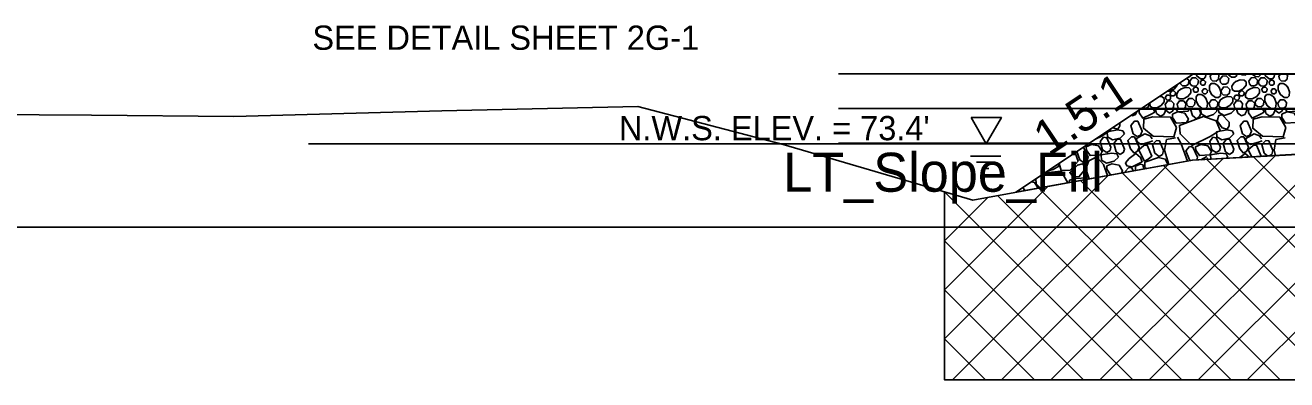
# Model space of a CAD drawing. Extents: x -14026 to 1303, y -10 to 9533.
# Drawn here: x 79.05 to 115.37, y 5995.6 to 6005.82 of the extents above; entities that cross this region are included whole.
import ezdxf

# ---------------------------------------------------------------- set-up
doc = ezdxf.new("R2010")
doc.units = 0
for name, color, linetype in [('Exist Cross Section Cell', 7, 'Continuous'), ('Exist XS Ground Line', 7, 'Continuous'), ('Old_Level_10', 7, 'Continuous'), ('Prop XS Side Slope Text', 7, 'Continuous'), ('Scratch_Level_0', 7, 'Continuous'), ('Scratch_Level_1', 7, 'Continuous'), ('Scratch_Level_3', 7, 'Continuous'), ('Scratch_Level_5', 7, 'Continuous')]:
    doc.layers.add(name, color=color, linetype=linetype)

msp = doc.modelspace()

# ---------------------------------------------------------------- linework, layer by layer
at = {"layer": 'Exist Cross Section Cell'}
msp.add_line((0, 6000), (150, 6000), dxfattribs=at)
at = {"layer": 'Exist XS Ground Line'}
msp.add_lwpolyline([(73.426, 6003.275), (80.955, 6003.228), (85.056, 6003.187), (91.045, 6003.354), (96.686, 6003.483), (100.866, 6002.389), (106.327, 6000.781), (112.649, 6001.933), (119.248, 6002.291)], dxfattribs=at)
at = {"layer": 'Old_Level_10'}
for p, q in [((107.565, 6001.007), (112.655, 6004.4)), ((113.16, 6004.354), (113.193, 6004.401)), ((115.139, 6004.354), (115.174, 6004.404)), ((111.155, 6003.4), (125.804, 6003.4)), ((111.531, 6003.4), (111.565, 6003.319)), ((113.345, 6003.4), (113.351, 6003.349)), ((113.858, 6003.4), (113.86, 6003.387)), ((114.678, 6003.4), (114.713, 6003.319)), ((110.921, 6003.207), (110.894, 6003.226)), ((110.286, 6002.821), (110.306, 6002.77)), ((112.889, 6001.946), (113.069, 6002.038)), ((113.07, 6002), (113.106, 6001.957)), ((113.668, 6002.021), (113.63, 6001.986)), ((108.784, 6001.82), (108.809, 6001.764)), ((109.106, 6001.287), (109.11, 6001.355)), ((107.828, 6001.055), (107.769, 6001.143))]:
    msp.add_line(p, q, dxfattribs=at)
msp.add_lwpolyline([(119.248, 6002.291), (117.01, 6002.178), (112.649, 6001.933), (107.565, 6001.007), (112.655, 6004.4), (127.732, 6004.426), (125.916, 6003.46), (123.411, 6002.115)], close=True, dxfattribs=at)
for points in [[(112.216, 6004.107), (112.215, 6004.097), (112.132, 6003.99), (112.003, 6003.926), (111.942, 6003.925)], [(112.492, 6004.291), (112.545, 6004.236), (112.534, 6004.128), (112.468, 6004.073), (112.362, 6004.08), (112.312, 6004.129), (112.305, 6004.167)], [(112.602, 6004.365), (112.577, 6004.339), (112.563, 6004.339)], [(112.572, 6004.208), (112.64, 6004.303), (112.747, 6004.309), (112.822, 6004.232), (112.811, 6004.124), (112.745, 6004.069), (112.639, 6004.076), (112.589, 6004.125), (112.573, 6004.208)], [(113.034, 6004.401), (113.028, 6004.333), (112.976, 6004.278), (112.882, 6004.28), (112.775, 6004.363), (112.757, 6004.4)], [(112.878, 6004.178), (112.919, 6004.236), (112.983, 6004.239), (113.028, 6004.193), (113.021, 6004.128), (112.982, 6004.095), (112.918, 6004.099), (112.888, 6004.128), (112.878, 6004.178)], [(113.417, 6004.033), (113.467, 6003.907), (113.457, 6003.792), (113.405, 6003.737), (113.311, 6003.739), (113.204, 6003.822), (113.14, 6003.951), (113.138, 6004.072), (113.187, 6004.14), (113.283, 6004.147), (113.37, 6004.091), (113.42, 6004.028)], [(113.387, 6004.401), (113.409, 6004.379), (113.399, 6004.27), (113.332, 6004.215), (113.226, 6004.223), (113.176, 6004.271), (113.16, 6004.354)], [(113.444, 6004.259), (113.512, 6004.355), (113.619, 6004.361), (113.694, 6004.284), (113.683, 6004.175), (113.616, 6004.12), (113.51, 6004.128), (113.461, 6004.176), (113.444, 6004.259)], [(113.927, 6004.402), (113.925, 6004.377), (113.872, 6004.322), (113.779, 6004.324), (113.679, 6004.402)], [(113.9, 6004.203), (114.025, 6004.253), (114.141, 6004.243), (114.196, 6004.191), (114.194, 6004.097), (114.111, 6003.99), (113.982, 6003.926), (113.861, 6003.924), (113.792, 6003.972), (113.786, 6004.069), (113.841, 6004.156), (113.905, 6004.206)], [(114.2, 6004.403), (114.178, 6004.384), (114.072, 6004.392), (114.061, 6004.403)], [(114.275, 6004.212), (114.342, 6004.307), (114.449, 6004.314), (114.524, 6004.236), (114.513, 6004.128), (114.447, 6004.073), (114.341, 6004.08), (114.291, 6004.129), (114.275, 6004.212)], [(114.609, 6004.403), (114.608, 6004.394), (114.556, 6004.339), (114.462, 6004.341), (114.382, 6004.403)], [(114.551, 6004.208), (114.618, 6004.303), (114.726, 6004.309), (114.8, 6004.232), (114.79, 6004.124), (114.723, 6004.069), (114.617, 6004.076), (114.567, 6004.125), (114.551, 6004.208)], [(115.013, 6004.404), (115.007, 6004.333), (114.954, 6004.278), (114.861, 6004.28), (114.754, 6004.363), (114.734, 6004.404)], [(114.857, 6004.178), (114.897, 6004.236), (114.962, 6004.239), (115.007, 6004.193), (115, 6004.128), (114.96, 6004.095), (114.897, 6004.099), (114.867, 6004.128), (114.857, 6004.178)], [(115.396, 6004.033), (115.446, 6003.907), (115.436, 6003.792), (115.384, 6003.737), (115.29, 6003.739), (115.183, 6003.822), (115.119, 6003.951), (115.117, 6004.072), (115.165, 6004.14), (115.262, 6004.147), (115.348, 6004.091), (115.399, 6004.028)], [(115.363, 6004.405), (115.388, 6004.379), (115.377, 6004.27), (115.311, 6004.215), (115.205, 6004.223), (115.155, 6004.271), (115.139, 6004.354)], [(111.708, 6003.769), (111.784, 6003.762), (111.839, 6003.71), (111.837, 6003.616), (111.754, 6003.51), (111.625, 6003.445), (111.503, 6003.443), (111.435, 6003.492), (111.429, 6003.583)], [(111.873, 6003.749), (111.913, 6003.807), (111.977, 6003.81), (112.022, 6003.764), (112.016, 6003.699), (111.976, 6003.666), (111.912, 6003.671), (111.882, 6003.7), (111.873, 6003.749)], [(112.011, 6003.866), (112.052, 6003.923), (112.116, 6003.927), (112.161, 6003.881), (112.154, 6003.816), (112.115, 6003.783), (112.051, 6003.787), (112.021, 6003.816), (112.011, 6003.866)], [(112.311, 6003.978), (112.437, 6004.028), (112.552, 6004.018), (112.607, 6003.966), (112.606, 6003.872), (112.522, 6003.766), (112.393, 6003.701), (112.272, 6003.699), (112.204, 6003.748), (112.197, 6003.844), (112.253, 6003.931), (112.316, 6003.982)], [(112.67, 6003.976), (112.711, 6004.034), (112.775, 6004.037), (112.82, 6003.991), (112.813, 6003.926), (112.774, 6003.893), (112.71, 6003.898), (112.68, 6003.927), (112.67, 6003.976)], [(113.037, 6003.716), (113.087, 6003.59), (113.077, 6003.475), (113.024, 6003.42), (112.931, 6003.421), (112.824, 6003.505), (112.76, 6003.633), (112.758, 6003.755), (112.806, 6003.823), (112.903, 6003.83), (112.989, 6003.774), (113.04, 6003.711)], [(112.935, 6003.929), (112.975, 6003.987), (113.04, 6003.99), (113.085, 6003.944), (113.078, 6003.879), (113.038, 6003.846), (112.975, 6003.85), (112.945, 6003.879), (112.935, 6003.929)], [(113.521, 6003.722), (113.647, 6003.772), (113.763, 6003.762), (113.817, 6003.71), (113.816, 6003.616), (113.732, 6003.51), (113.604, 6003.445), (113.482, 6003.443), (113.414, 6003.492), (113.407, 6003.588), (113.463, 6003.675), (113.526, 6003.725)], [(113.474, 6003.945), (113.541, 6004.04), (113.649, 6004.046), (113.723, 6003.969), (113.713, 6003.861), (113.646, 6003.805), (113.54, 6003.813), (113.49, 6003.861), (113.474, 6003.945)], [(113.851, 6003.749), (113.892, 6003.807), (113.956, 6003.81), (114.001, 6003.764), (113.994, 6003.699), (113.955, 6003.666), (113.891, 6003.671), (113.861, 6003.7), (113.851, 6003.749)], [(113.99, 6003.866), (114.03, 6003.923), (114.095, 6003.927), (114.14, 6003.881), (114.133, 6003.816), (114.093, 6003.783), (114.03, 6003.787), (114, 6003.816), (113.99, 6003.866)], [(114.29, 6003.978), (114.416, 6004.028), (114.531, 6004.018), (114.586, 6003.966), (114.584, 6003.872), (114.501, 6003.766), (114.372, 6003.701), (114.251, 6003.699), (114.182, 6003.748), (114.176, 6003.844), (114.231, 6003.931), (114.295, 6003.982)], [(114.649, 6003.976), (114.689, 6004.034), (114.754, 6004.037), (114.798, 6003.991), (114.792, 6003.926), (114.752, 6003.893), (114.689, 6003.898), (114.659, 6003.927), (114.649, 6003.976)], [(115.015, 6003.716), (115.065, 6003.59), (115.055, 6003.475), (115.003, 6003.42), (114.909, 6003.421), (114.803, 6003.505), (114.738, 6003.633), (114.736, 6003.755), (114.785, 6003.823), (114.882, 6003.83), (114.968, 6003.774), (115.019, 6003.711)], [(114.914, 6003.929), (114.954, 6003.987), (115.019, 6003.99), (115.063, 6003.944), (115.057, 6003.879), (115.017, 6003.846), (114.953, 6003.85), (114.924, 6003.879), (114.914, 6003.929)], [(111.401, 6003.564), (111.393, 6003.491), (111.327, 6003.436), (111.221, 6003.443), (111.22, 6003.444)], [(111.734, 6003.203), (111.618, 6003.28), (111.592, 6003.4)], [(111.861, 6003.4), (111.878, 6003.359), (111.826, 6003.245), (111.734, 6003.203)], [(111.868, 6003.539), (111.935, 6003.635), (112.043, 6003.641), (112.117, 6003.564), (112.107, 6003.455), (112.042, 6003.402)], [(112.019, 6003.402), (111.934, 6003.408), (111.884, 6003.456), (111.868, 6003.539)], [(111.986, 6003.285), (111.882, 6003.374), (111.877, 6003.4)], [(112.108, 6003.4), (112.077, 6003.345), (111.986, 6003.285)], [(112.555, 6003.4), (112.527, 6003.35), (112.228, 6003.331), (112.186, 6003.4)], [(112.215, 6003.543), (112.282, 6003.639), (112.39, 6003.645), (112.464, 6003.568), (112.453, 6003.459), (112.387, 6003.404), (112.281, 6003.412), (112.231, 6003.46), (112.215, 6003.543)], [(112.476, 6003.613), (112.543, 6003.709), (112.65, 6003.715), (112.725, 6003.638), (112.714, 6003.529), (112.648, 6003.474), (112.542, 6003.482), (112.492, 6003.53), (112.476, 6003.613)], [(112.765, 6003.128), (112.649, 6003.217), (112.599, 6003.4)], [(112.842, 6003.4), (112.89, 6003.289), (112.856, 6003.194), (112.765, 6003.128)], [(113.351, 6003.349), (113.261, 6003.251), (113.057, 6003.18), (112.904, 6003.268), (112.893, 6003.4)], [(113.134, 6003.575), (113.201, 6003.67), (113.308, 6003.677), (113.383, 6003.599), (113.372, 6003.491), (113.306, 6003.436), (113.2, 6003.443), (113.15, 6003.492), (113.134, 6003.575)], [(113.86, 6003.387), (113.77, 6003.289), (113.566, 6003.218), (113.413, 6003.306), (113.405, 6003.4)], [(113.847, 6003.539), (113.914, 6003.635), (114.022, 6003.641), (114.096, 6003.564), (114.085, 6003.455), (114.025, 6003.405)], [(113.951, 6003.405), (113.913, 6003.408), (113.863, 6003.456), (113.847, 6003.539)], [(114.068, 6003.207), (113.953, 6003.29), (113.919, 6003.4)], [(114.195, 6003.4), (114.212, 6003.363), (114.161, 6003.248), (114.068, 6003.207)], [(114.194, 6003.543), (114.261, 6003.639), (114.368, 6003.645), (114.443, 6003.568), (114.432, 6003.459), (114.368, 6003.406)], [(114.343, 6003.406), (114.26, 6003.412), (114.21, 6003.46), (114.194, 6003.543)], [(114.713, 6003.319), (114.609, 6003.258), (114.37, 6003.142), (114.263, 6003.3), (114.26, 6003.382), (114.302, 6003.4)], [(114.455, 6003.613), (114.522, 6003.709), (114.629, 6003.715), (114.704, 6003.638), (114.693, 6003.529), (114.627, 6003.474), (114.521, 6003.482), (114.471, 6003.53), (114.455, 6003.613)], [(114.881, 6003.203), (114.766, 6003.28), (114.74, 6003.4)], [(115.009, 6003.4), (115.025, 6003.359), (114.974, 6003.245), (114.881, 6003.203)], [(115.134, 6003.285), (115.03, 6003.374), (115.024, 6003.4)], [(115.112, 6003.575), (115.179, 6003.67), (115.287, 6003.677), (115.361, 6003.599), (115.351, 6003.491), (115.284, 6003.436), (115.178, 6003.443), (115.128, 6003.492), (115.112, 6003.575)], [(115.255, 6003.4), (115.225, 6003.345), (115.134, 6003.285)], [(115.702, 6003.4), (115.675, 6003.35), (115.375, 6003.331), (115.334, 6003.4)], [(111.063, 6002.613), (110.947, 6002.696), (110.875, 6002.937), (110.983, 6003.054), (111.076, 6003.058), (111.207, 6002.769), (111.155, 6002.655), (111.063, 6002.613)], [(111.05, 6003.33), (111.013, 6003.248), (110.921, 6003.207)], [(111.565, 6003.319), (111.461, 6003.258), (111.222, 6003.142), (111.116, 6003.3), (111.113, 6003.372)], [(111.253, 6003.118), (111.513, 6003.185), (112.02, 6003.168), (112.188, 6002.875), (112.118, 6002.609), (111.517, 6002.623), (111.238, 6002.855), (111.253, 6003.118)], [(112.074, 6003.256), (112.221, 6003.324), (112.429, 6003.283), (112.536, 6003.118), (112.484, 6003.022), (112.184, 6003.004), (112.078, 6003.162), (112.074, 6003.256)], [(113.392, 6002.761), (113.166, 6002.614), (112.633, 6002.355), (112.294, 6002.691), (112.277, 6002.935), (112.974, 6003.188), (113.336, 6003.065), (113.454, 6002.77)], [(113.649, 6002.83), (113.505, 6002.864), (113.358, 6003.066), (113.409, 6003.217), (113.503, 6003.236), (113.708, 6003.025), (113.711, 6002.924), (113.649, 6002.83)], [(114.211, 6002.613), (114.095, 6002.696), (114.022, 6002.937), (114.13, 6003.054), (114.224, 6003.058), (114.355, 6002.769), (114.303, 6002.655), (114.211, 6002.613)], [(114.4, 6003.118), (114.66, 6003.185), (115.168, 6003.168), (115.336, 6002.875), (115.265, 6002.609), (114.664, 6002.623), (114.386, 6002.855), (114.4, 6003.118)], [(115.222, 6003.256), (115.369, 6003.324), (115.577, 6003.283), (115.684, 6003.118), (115.631, 6003.022), (115.332, 6003.004), (115.225, 6003.162), (115.222, 6003.256)], [(110.244, 6002.761), (110.019, 6002.614), (109.861, 6002.537)], [(110.694, 6002.689), (110.567, 6002.571), (110.351, 6002.519), (110.21, 6002.601), (110.197, 6002.75), (110.495, 6002.806), (110.646, 6002.781), (110.694, 6002.689)], [(110.501, 6002.83), (110.358, 6002.864), (110.355, 6002.867)], [(110.561, 6003.004), (110.563, 6002.924), (110.501, 6002.83)], [(111.514, 6002.492), (111.41, 6002.45), (111.168, 6002.384), (111.052, 6002.486), (111.042, 6002.561), (111.281, 6002.689), (111.433, 6002.639), (111.493, 6002.548)], [(113.842, 6002.689), (113.715, 6002.571), (113.498, 6002.519), (113.357, 6002.601), (113.345, 6002.75), (113.643, 6002.806), (113.794, 6002.781), (113.842, 6002.689)], [(114.662, 6002.492), (114.557, 6002.45), (114.316, 6002.384), (114.199, 6002.486), (114.19, 6002.561), (114.429, 6002.689), (114.581, 6002.639), (114.641, 6002.548)], [(109.515, 6002.307), (109.518, 6002.307), (109.649, 6002.018), (109.621, 6001.923), (109.511, 6001.862)], [(109.593, 6002.316), (109.741, 6002.385), (109.949, 6002.343), (110.055, 6002.179), (110.003, 6002.083), (109.704, 6002.064), (109.597, 6002.223), (109.593, 6002.316)], [(110.187, 6002.15), (110.065, 6002.232), (109.999, 6002.473), (110.094, 6002.596), (110.189, 6002.581), (110.306, 6002.311), (110.279, 6002.216), (110.187, 6002.15)], [(110.574, 6002.093), (110.452, 6002.175), (110.386, 6002.416), (110.488, 6002.539), (110.582, 6002.525), (110.699, 6002.254), (110.666, 6002.159), (110.574, 6002.093)], [(110.977, 6002.136), (110.871, 6002.263), (110.787, 6002.503), (110.895, 6002.602), (110.983, 6002.605), (111.12, 6002.31), (111.068, 6002.196), (110.977, 6002.136)], [(111.267, 6001.902), (111.226, 6001.994), (111.11, 6002.233), (111.255, 6002.358), (111.348, 6002.362), (111.48, 6002.048), (111.377, 6001.963), (111.267, 6001.902)], [(111.693, 6002.038), (111.57, 6002.139), (111.504, 6002.38), (111.612, 6002.497), (111.706, 6002.489), (111.818, 6002.212), (111.785, 6002.098), (111.693, 6002.038)], [(111.968, 6001.808), (111.851, 6002.217), (111.908, 6002.526), (112.168, 6002.574)], [(112.224, 6002.595), (112.326, 6002.399), (112.506, 6001.906)], [(112.585, 6001.921), (112.562, 6001.94), (112.463, 6002.205), (112.571, 6002.322), (112.666, 6002.307), (112.796, 6002.018), (112.773, 6001.939)], [(112.741, 6002.316), (112.888, 6002.385), (113.096, 6002.343), (113.203, 6002.179), (113.151, 6002.083), (112.851, 6002.064), (112.745, 6002.223), (112.741, 6002.316)], [(113.335, 6002.15), (113.213, 6002.232), (113.147, 6002.473), (113.242, 6002.596), (113.336, 6002.581), (113.454, 6002.311), (113.426, 6002.216), (113.335, 6002.15)], [(113.722, 6002.093), (113.6, 6002.175), (113.534, 6002.416), (113.635, 6002.539), (113.73, 6002.525), (113.847, 6002.254), (113.813, 6002.159), (113.722, 6002.093)], [(114.124, 6002.136), (114.019, 6002.263), (113.934, 6002.503), (114.043, 6002.602), (114.13, 6002.605), (114.267, 6002.31), (114.216, 6002.196), (114.124, 6002.136)], [(114.358, 6002.025), (114.257, 6002.233), (114.402, 6002.358), (114.496, 6002.362), (114.628, 6002.048), (114.617, 6002.039)], [(114.826, 6002.051), (114.718, 6002.139), (114.652, 6002.38), (114.76, 6002.497), (114.854, 6002.489), (114.965, 6002.212), (114.932, 6002.098), (114.864, 6002.053)], [(115.043, 6002.062), (114.999, 6002.217), (115.055, 6002.526), (115.316, 6002.574)], [(109.271, 6002.144), (109.361, 6001.9), (109.133, 6001.647), (108.871, 6001.63), (108.812, 6001.838)], [(109.511, 6001.862), (109.414, 6001.94), (109.325, 6002.18)], [(109.68, 6001.392), (109.585, 6001.68), (109.67, 6001.909), (109.921, 6002.038)], [(109.922, 6002), (110.087, 6001.807), (110.207, 6001.488)], [(110.52, 6002.021), (110.393, 6001.903), (110.177, 6001.851), (110.036, 6001.933), (110.023, 6002.082), (110.321, 6002.138), (110.473, 6002.113), (110.52, 6002.021)], [(110.726, 6001.855), (110.827, 6001.976), (111.021, 6002.126), (111.158, 6002.013), (111.201, 6001.885), (110.914, 6001.743), (110.762, 6001.774), (110.726, 6001.855)], [(111.319, 6001.69), (111.283, 6001.724), (111.276, 6001.874), (111.678, 6002.009), (111.867, 6001.966), (111.939, 6001.803)], [(113.181, 6001.961), (113.171, 6002.082), (113.469, 6002.138), (113.62, 6002.113), (113.668, 6002.021)], [(114.014, 6002.007), (114.169, 6002.126), (114.295, 6002.022)], [(108.413, 6001.572), (108.876, 6001.615), (109.067, 6001.28)], [(108.809, 6001.764), (108.644, 6001.663), (108.498, 6001.629)], [(109.548, 6001.757), (109.525, 6001.627), (109.391, 6001.458), (109.215, 6001.449), (109.117, 6001.579), (109.338, 6001.786), (109.49, 6001.831), (109.548, 6001.757)], [(110.184, 6001.765), (110.331, 6001.827), (110.539, 6001.785), (110.64, 6001.621), (110.607, 6001.561)], [(110.318, 6001.508), (110.288, 6001.506), (110.188, 6001.671), (110.184, 6001.765)], [(110.721, 6001.581), (110.715, 6001.603), (110.816, 6001.726), (110.911, 6001.711), (110.949, 6001.623)], [(111.013, 6001.635), (111.01, 6001.758), (111.144, 6001.818), (111.228, 6001.794), (111.242, 6001.676)], [(108.011, 6001.304), (108.105, 6001.286), (108.21, 6001.124)], [(108.268, 6001.135), (108.153, 6001.254), (108.144, 6001.393)], [(109.11, 6001.355), (109.29, 6001.4), (109.608, 6001.419), (109.625, 6001.382)]]:
    msp.add_lwpolyline(points, dxfattribs=at)
at = {"layer": 'Prop XS Side Slope Text'}
for p, q in [((106.263, 6002.046), (107.138, 6002.046)), ((106.438, 6001.871), (106.963, 6001.871)), ((106.613, 6001.696), (106.788, 6001.696))]:
    msp.add_line(p, q, dxfattribs=at)
msp.add_lwpolyline([(106.277, 6003.159), (107.152, 6003.159), (106.714, 6002.4)], close=True, dxfattribs=at)
at = {"layer": 'Scratch_Level_1'}
msp.add_line((87.209, 6002.4), (138.363, 6002.4), dxfattribs=at)
at = {"layer": 'Scratch_Level_3'}
for p, q in [((127.732, 6004.426), (102.458, 6004.426)), ((125.853, 6003.426), (102.458, 6003.426)), ((109.721, 6002.426), (102.458, 6002.426))]:
    msp.add_line(p, q, dxfattribs=at)
at = {"layer": 'Scratch_Level_5'}
for p, q in [((107.159, 5995.6), (113.54, 6001.981)), ((108.574, 5995.6), (115.036, 6002.062)), ((109.988, 5995.6), (116.531, 6002.143)), ((111.402, 5995.6), (118.026, 6002.224)), ((112.816, 5995.6), (119.496, 6002.28)), ((113.063, 6001.955), (119.418, 5995.6)), ((114.23, 5995.6), (120.854, 6002.223)), ((114.404, 6002.028), (120.832, 5995.6)), ((105.745, 5995.6), (111.95, 6001.805)), ((110.625, 6001.564), (116.589, 5995.6)), ((111.822, 6001.782), (118.003, 5995.6)), ((105.51, 5996.779), (110.221, 6001.49)), ((109.429, 6001.346), (115.175, 5995.6)), ((105.51, 5998.194), (108.492, 6001.176)), ((105.51, 6001.022), (110.932, 5995.6)), ((105.51, 5999.608), (106.763, 6000.861)), ((107.036, 6000.91), (112.347, 5995.6)), ((108.232, 6001.128), (113.761, 5995.6)), ((105.51, 5999.608), (109.518, 5995.6)), ((105.51, 5998.194), (108.104, 5995.6)), ((105.51, 5996.779), (106.69, 5995.6))]:
    msp.add_line(p, q, dxfattribs=at)
msp.add_lwpolyline([(123.411, 6002.115), (123.411, 5995.6), (105.51, 5995.6), (105.51, 6001.022), (106.327, 6000.781), (112.649, 6001.933), (119.248, 6002.291)], close=True, dxfattribs=at)

# ---------------------------------------------------------------- texts
at = {"layer": 'Old_Level_10'}
msp.add_text('SEE DETAIL SHEET 2G-1', height=0.7, dxfattribs=at).set_placement((87.317, 6005.114))
at = {"layer": 'Prop XS Side Slope Text'}
msp.add_text('1.5:1', height=1, rotation=33.6901, dxfattribs=at).set_placement((108.519, 6002.033))
msp.add_text("N.W.S. ELEV. = 73.4'", height=0.7, dxfattribs=at).set_placement((96.141, 6002.507))
at = {"layer": 'Scratch_Level_0'}
msp.add_text('LT_Slope_Fill', height=1.125, dxfattribs=at).set_placement((100.87, 6001.022))

doc.saveas('drawing.dxf')
